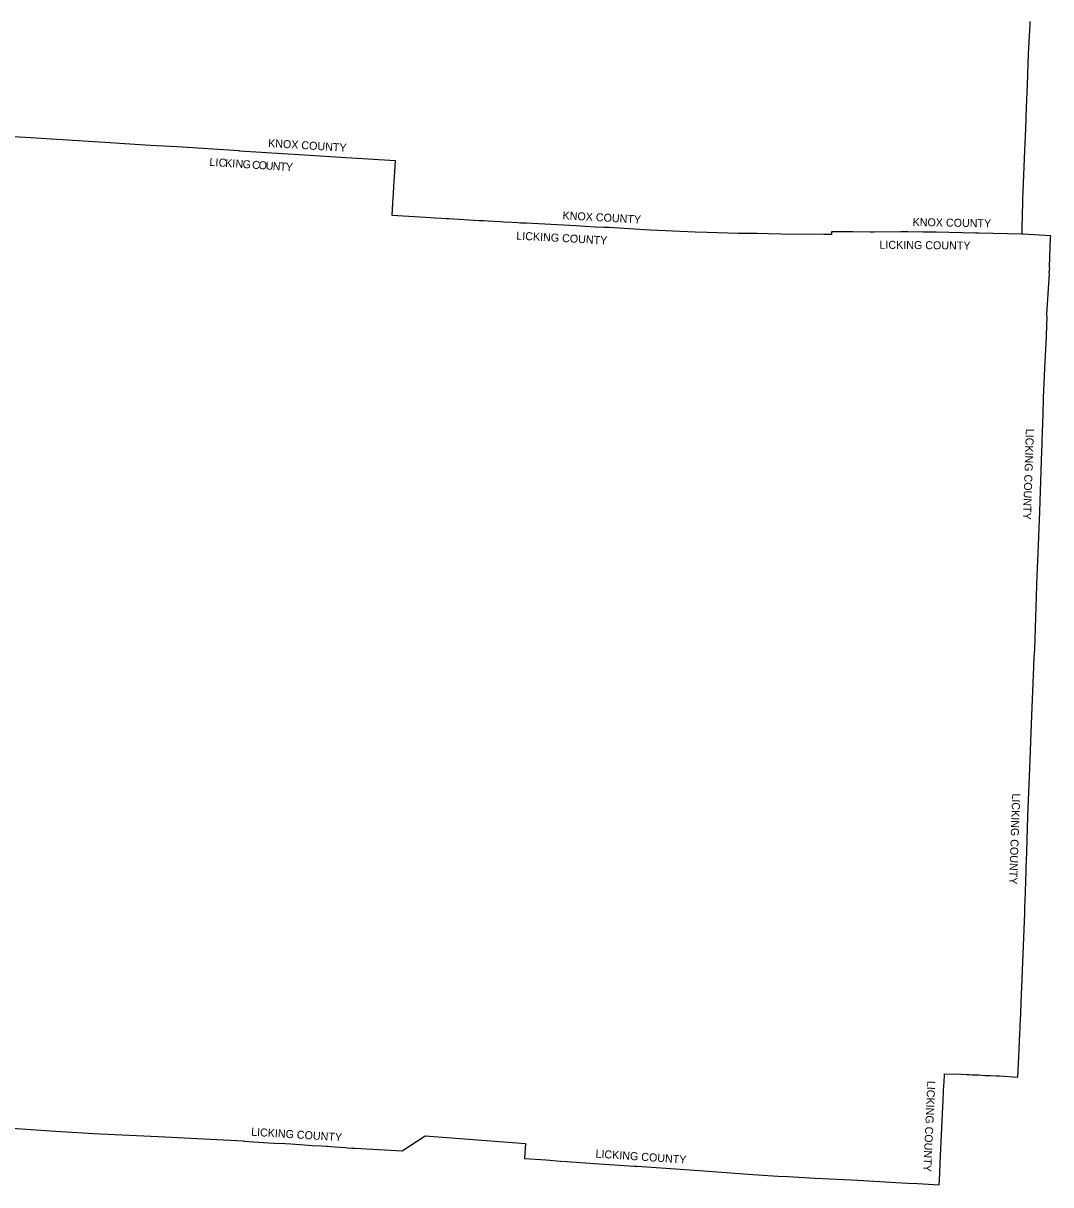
# Model space of a CAD drawing. Extents: x 1674899 to 2057726, y 653888 to 988278.
# Drawn here: x 1928708 to 2057032, y 696951 to 842053 of the extents above; entities that cross this region are included whole.
import ezdxf

# ---------------------------------------------------------------- set-up
doc = ezdxf.new("R2010")
doc.units = 0
doc.layers.add('GM_X_Adjacent_County', color=7, linetype='Continuous')
doc.layers.add('GM_X_Adjacent_County_Text', color=7, linetype='Continuous')

msp = doc.modelspace()

# ---------------------------------------------------------------- linework, layer by layer
at = {"layer": 'GM_X_Adjacent_County'}
for points in [[(2054411, 842272), (2054399, 841942), (2054222, 838243), (2054175, 836924), (2054096, 834376), (2053974, 831534), (2053892, 828885), (2053768, 826142), (2053521, 820038), (2053499, 819706), (2053421, 816435), (2053420, 816169), (2053400, 815687), (2048066, 815835), (2047646, 815843), (2042725, 815935), (2041130, 815961), (2039197, 815992), (2038298, 816006), (2034985, 815966), (2034493, 815970), (2032253, 815990), (2029643, 815984), (2029631, 815665), (2029362, 815671), (2028709, 815661), (2023356, 815714), (2021728, 815742), (2020383, 815765), (2017999, 815806), (2014117, 815901), (2012614, 815938), (2008904, 816114), (2007002, 816215), (2006296, 816251), (2001880, 816522), (2001221, 816534), (2000194, 816593), (1998869, 816653), (1997718, 816724), (1993053, 816984), (1991541, 817066), (1991301, 817077), (1990962, 817091), (1990909, 817093), (1990797, 817097), (1990486, 817113), (1989752, 817152), (1988744, 817207), (1988298, 817233), (1986763, 817318), (1986195, 817348), (1985662, 817383), (1981878, 817613), (1981516, 817615), (1980999, 817647), (1980171, 817698), (1978931, 817776), (1974782, 818034), (1974872, 819557), (1974905, 820235), (1975185, 824849), (1968995, 825250), (1968380, 825282), (1963814, 825573), (1961147, 825745), (1958413, 825903), (1955710, 826085), (1955666, 826092), (1953054, 826262), (1948593, 826569), (1947878, 826617), (1944570, 826798), (1940743, 827038), (1939557, 827120), (1937526, 827240), (1933604, 827484), (1932924, 827522), (1929658, 827739), (1926023, 827933)], [(1926704, 704049), (1932110, 703691), (1933445, 703603), (1937496, 703356), (1940133, 703233), (1945542, 702971), (1956177, 702424), (1956246, 702400), (1959326, 702192), (1960069, 702146), (1961405, 702089), (1962142, 702048), (1963274, 701972), (1964839, 701877), (1965938, 701805), (1966607, 701763), (1966649, 701762), (1966808, 701758), (1967105, 701727), (1967603, 701692), (1968964, 701601), (1969207, 701585), (1969838, 701543), (1970120, 701524), (1976043, 701175), (1978896, 703059), (1991426, 702096), (1991315, 700214), (1994025, 700047), (1995788, 699915), (1996556, 699862), (1998340, 699731), (1999991, 699615), (2005010, 699291), (2005388, 699262), (2010765, 698883), (2014237, 698633), (2019826, 698250), (2022930, 698031), (2024237, 697978), (2027603, 697795), (2032964, 697511), (2037684, 697249), (2039211, 697158), (2040417, 697097), (2043100, 696951), (2043174, 698365), (2043240, 699701), (2043605, 707562), (2043609, 707649), (2043698, 709467), (2043703, 709651), (2043750, 710828), (2045826, 710751), (2046565, 710712), (2046823, 710711), (2047222, 710696), (2047504, 710677), (2047627, 710683), (2048006, 710664), (2048414, 710648), (2048814, 710618), (2049234, 710593), (2049512, 710584), (2050233, 710574), (2050634, 710559), (2052900, 710410), (2052902, 710453), (2052965, 711140), (2052971, 711258), (2052997, 712030), (2053002, 712165), (2053006, 712211), (2053011, 712276), (2053013, 712309), (2053020, 712453), (2053027, 712618), (2053035, 712851), (2053047, 713067), (2053056, 713273), (2053071, 713603), (2053082, 713799), (2053089, 713999), (2053093, 714078), (2053096, 714173), (2053100, 714274), (2053104, 714392), (2053110, 714504), (2053115, 714601), (2053130, 714913), (2053132, 714994), (2053136, 715092), (2053140, 715190), (2053143, 715256), (2053144, 715285), (2053147, 715337), (2053154, 715453), (2053160, 715581), (2053168, 715713), (2053175, 715844), (2053184, 715990), (2053189, 716090), (2053199, 716269), (2053202, 716368), (2053206, 716442), (2053206, 716521), (2053210, 716642), (2053212, 716727), (2053216, 716829), (2053219, 716926), (2053223, 717037), (2053227, 717104), (2053230, 717187), (2053234, 717273), (2053238, 717331), (2053242, 717396), (2053254, 717560), (2053261, 717674), (2053269, 717877), (2053272, 717937), (2053275, 718001), (2053277, 718051), (2053280, 718133), (2053283, 718198), (2053287, 718297), (2053289, 718354), (2053291, 718411), (2053295, 718509), (2053304, 718721), (2053312, 718916), (2053325, 719144), (2053329, 719210), (2053333, 719259), (2053335, 719308), (2053340, 719475), (2053339, 719545), (2053340, 719583), (2053343, 719632), (2053345, 719646), (2053347, 719659), (2053349, 719668), (2053503, 723734), (2053781, 730868), (2053813, 731645), (2053836, 732325), (2053962, 736094), (2053972, 736685), (2054045, 738417), (2054047, 738432), (2054048, 738446), (2054049, 738461), (2054049, 738491), (2054050, 738518), (2054050, 738546), (2054051, 738564), (2054051, 738571), (2054052, 738582), (2054056, 738594), (2054183, 742975), (2054401, 748988), (2054673, 755556), (2054916, 761641), (2054919, 761750), (2054960, 762935), (2055001, 763323), (2055024, 763817), (2055344, 773144), (2055389, 773960), (2055514, 776840), (2055675, 781040), (2055921, 788683), (2055947, 789303), (2055950, 789428), (2055968, 789562), (2055974, 789769), (2056081, 793304), (2056132, 795032), (2056126, 795080), (2056131, 795278), (2056352, 799837), (2056382, 800495), (2056483, 802899), (2056539, 804360), (2056569, 805221), (2056542, 805719), (2056862, 810765), (2056847, 810908), (2056896, 811456), (2056881, 811520), (2056883, 811617), (2057020, 815247), (2057032, 815483), (2053533, 815684), (2053400, 815687), (2048066, 815835), (2047646, 815843), (2042725, 815935), (2041130, 815961), (2039197, 815992), (2038298, 816006), (2034985, 815966), (2034493, 815970), (2032253, 815990), (2029643, 815984), (2029631, 815665), (2029362, 815671), (2028709, 815661), (2023356, 815714), (2021728, 815742), (2020383, 815765), (2017999, 815806), (2014117, 815901), (2012614, 815938), (2008904, 816114), (2007002, 816215), (2006296, 816251), (2001880, 816522), (2001221, 816534), (2000194, 816593), (1998869, 816653), (1997718, 816724), (1993053, 816984), (1991541, 817066), (1991301, 817077), (1990962, 817091), (1990909, 817093), (1990797, 817097), (1990486, 817113), (1989752, 817152), (1988744, 817207), (1988298, 817233), (1986763, 817318), (1986195, 817348), (1985662, 817383), (1981878, 817613), (1981516, 817615), (1980999, 817647), (1980171, 817698), (1978931, 817776), (1974782, 818034), (1974872, 819557), (1974905, 820235), (1975185, 824849), (1968995, 825250), (1968380, 825282), (1963814, 825573), (1961147, 825745), (1958413, 825903), (1955710, 826085), (1955666, 826092), (1953054, 826262), (1948593, 826569), (1947878, 826617), (1944570, 826798), (1940743, 827038), (1939557, 827120), (1937526, 827240), (1933604, 827484), (1932924, 827522), (1929658, 827739), (1926023, 827933)]]:
    msp.add_lwpolyline(points, dxfattribs=at)

# ---------------------------------------------------------------- texts
at = {"layer": 'GM_X_Adjacent_County_Text'}
for s, rotation, p in [('KNOX COUNTY', 356.44668, (1959266, 826596)), ('L', 356.2032, (1951934, 824244)), ('I', 356.20513, (1952681, 824194)), ('C', 356.20007, (1953089, 824167)), ('K', 356.18368, (1953901, 824113)), ('I', 356.14981, (1954783, 824054)), ('N', 356.07909, (1955191, 824027)), ('G', 356.38052, (1956080, 823966)), ('C', 356.40177, (1957266, 823891)), ('O', 356.40358, (1958078, 823840)), ('U', 356.40582, (1958961, 823785)), ('N', 356.40494, (1959844, 823729)), ('T', 356.4041, (1960726, 823674)), ('Y', 356.40386, (1961473, 823627)), ('KNOX COUNTY', 356.93255, (1996041, 817559)), ('KNOX COUNTY', 358.98503, (2039771, 816724)), ('LICKING COUNTY', 356.89082, (1990268, 815032)), ('LICKING COUNTY', 359.42004, (2035634, 813885)), ('LICKING COUNTY', 268.09344, (2053932, 791412)), ('LICKING COUNTY', 267.97506, (2052225, 745852)), ('LICKING COUNTY', 267.36629, (2041621, 709953)), ('LICKING COUNTY', 356.46927, (1957144, 703082)), ('LICKING COUNTY', 356.12964, (2000154, 700350))]:
    msp.add_text(s, height=1000, rotation=rotation, dxfattribs=at).set_placement(p)

doc.saveas('drawing.dxf')
